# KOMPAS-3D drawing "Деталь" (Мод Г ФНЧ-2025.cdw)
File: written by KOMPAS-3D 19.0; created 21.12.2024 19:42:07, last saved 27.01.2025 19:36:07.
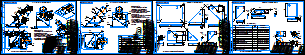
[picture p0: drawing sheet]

Sheets 1-4: A3, landscape

Document properties: Автор: Степан; Масса: 25.9973; Форматы листов документа: 4xA3; Полное имя файла: ..\Модуль Г на РЧ Степана.m3d

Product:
- Part/product: Деталь
    Материал: Сталь 20  ГОСТ 1050-2013 (density 7859 kg/m3)
    Масса: 25.9973
  - Body: Тело 16
      Масса: 8.25404
  - Body: Тело 1
      Масса: 8.25404
  - Body: Тело 2
      Масса: 4.68141
  - Body: Тело 3
      Масса: 5.34823
  - Body: Тело 4
      Масса: 1.5207
  - Body: Тело 5
      Масса: 1.51272
  - Body: Тело 6
      Масса: 0.578914
  - Body: Тело 7
      Масса: 0.0341336
  - Body: Тело 10
      Масса: 0.941666
  - Body: Тело 11
      Масса: 0.980833
  - Body: Тело 12
      Масса: 5.34823
  - Body: Тело 13
      Масса: 0.710329
  - Body: Тело 14
      Масса: 1.21209
  - Body: Тело 15
      Масса: 0.222208

Title block, sheet 1: Наименование: Модуль Г / ФНЧ-2025; designation: Процесс сварки 135 (МП); Материал: Ст3, 09Г2С; Масса: 26; sheet number: 1; Количество листов документа: 4; organisation: Чемпионат ПМ / "Профессионалы"; Форматы листов документа: A3; stored path: C:\Users\Степан\Desktop\Модуль Г Степанов.cdw; Разработал: Степанов С.С.; Проверил: Калашников В.А.; Утвердил: Дюкова С. В.
Title block, sheet 2: sheet number: 2
Title block, sheet 3: sheet number: 3
Title block, sheet 4: sheet number: 4

Views: Вид А, Вид Б, Вид В, Спереди 1, Спереди, Вид Г, Вид Д, Вид Е, Проекционный вид 2, Изометрия 5, Изометрия, Спереди 7, Проекционный вид 8, Проекционный вид 9
Referenced files in C:\Users\Степан\Desktop\Модули на РЧ\: Модуль Г на РЧ Степана.m3d
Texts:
  Все размеры на чертеже указаны в миллиметрах
  Сборочно-сварочный чертеж
  Технические условия:
  1. Произвести сборку консрукции в любом
  пространственном положении;
  2. Длина прихваток не более 15 мм, внутри
  конструкции прихватки не допустимы;
  3. Перед началом сварки конструкцию
  предоставить на осмотр, без узла из
  деталей "13"+"12"+"11"+"11"+"5".
  Все расмеры на чертеже указаны в миллиметрах
  № дет.
  Наименование, размеры
  Кол-во,
  шт.
  Пластина 10х280х380
  см. чертеж
  Пластина 10х236х210
  разделка 20°, см. чертеж
  Пластина 10х262х210 с отв.  30 мм
  Пластина  60х10 (заглушка)
  Пластина 10х163х250 с отв.  75
  Пластина 10х160х160
  Пластина 10х165х113
  Пластина 10х195.5х113
  Пластина 10х58,34х218,34
  Пластина 10х165х210
  Труба  114х8 - 75
  разделка 30°, см. чертеж
  Пластина  98х10 с отв.  15 мм (заглушка)
  Труба  21.,5х2,8 - 40
  Деталировочный чертеж
  Пользовательская 6
  Пользовательская
  Техничские условия:
  1. Сварку конструкции производить
  относительно базовой пластины "1".
  Наклонять конструкцию в процессе
  сварки запрещено, допускается вращать
  вокруг вертикальной оси. Сварка на
  спуск запрещена.
  2. Сварку угловых и тавровых соединений
  выполнить в 2 слоя, 3 прохода
  (облицовочный слой в два прохода) кроме
  сваррного шва №7.
  3. Воздействие образивных материалов,
  режущего инструмента и оборудования
  для облицовочных сварных швов,
  запрещены.
  № св. шва
  Стандарт и обозначение
  Кол-во
  ГОСТ 14771-76-Т1- 8 +2
  ГОСТ 14771-76-Т1- 6 +2
  ГОСТ 23518-79-Т5- 8 +2
  ГОСТ 14771-76-С17
  ГОСТ 16037-80-С17
  ГОСТ 23518-79-Т5- 10
  ГОСТ 14771-76-Т1- 4 +2
Dimensions and other numbers on the sheet: 54 2; 56 2; 4; 8; 9; 10; 11; 13; 25 2; 12; 1; 2; 3; 6; 7; 48 2; 40; 280; 380; 26; 262; 52; 210; 30; 65; 84; 60; 163; 81,5; 105; 75; 5; 250; 160; 236; 165; 113; 195,5; 82,5; 218,34; 114; 98; 15; 21,5; 1/2"; 58,34; 1:3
